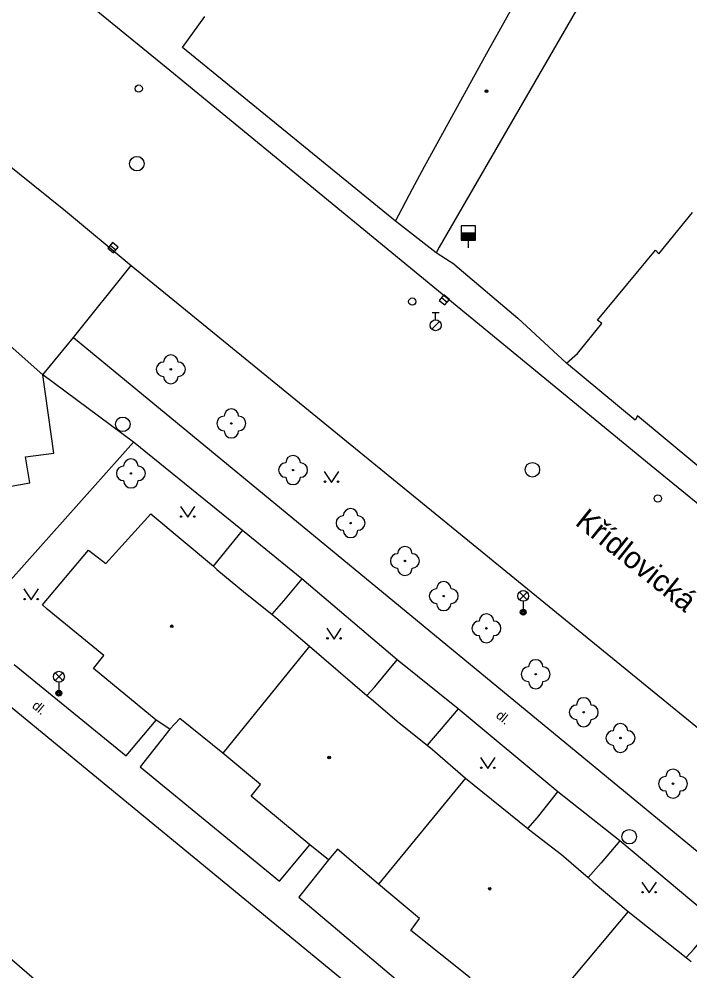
# Model space of a CAD drawing. Extents: x -598932 to -598196, y -1162207 to -1161504.
# Drawn here: x -598487.7 to -598441.5, y -1161944.1 to -1161878.5 of the extents above; entities that cross this region are included whole.
import ezdxf

# ---------------------------------------------------------------- set-up
doc = ezdxf.new("R2010")
doc.units = 0
for name, color, linetype in [('Level 22', 7, 'Continuous'), ('Level 27', 7, 'Continuous'), ('Level 28', 7, 'Continuous'), ('Level 33', 7, 'Continuous'), ('Level 36', 7, 'Continuous'), ('Level 39', 7, 'Continuous'), ('specificka linie pasportu komunikaci', 7, 'Continuous'), ('TM - budovy zdene_ betonove - VP', 7, 'Continuous'), ('TM - chodniky - VP', 7, 'Continuous'), ('TM - komunikace - VP', 7, 'Continuous'), ('TM - plot dreveny_ kovovy - VP', 7, 'Continuous'), ('TM - plot zdeny_ ohradni zed - VP', 7, 'Continuous'), ('TM - popis povrchu', 7, 'Continuous'), ('TM - rozhrani ploch obecne - VP', 7, 'Continuous'), ('TM - vjezd na pozemek', 7, 'Continuous'), ('ulice', 7, 'Continuous')]:
    doc.layers.add(name, color=color, linetype=linetype)

msp = doc.modelspace()

# ---------------------------------------------------------------- linework, layer by layer
at = {"layer": 'Level 22'}
for centre in [(-598477.28, -1161902.63), (-598473.11, -1161906.36), (-598480.03, -1161909.8), (-598468.86, -1161909.57), (-598464.9, -1161913.22), (-598461.16, -1161915.83), (-598458.48, -1161918.25), (-598455.54, -1161920.47), (-598452.15, -1161923.63), (-598448.84, -1161926.25), (-598446.31, -1161928.02), (-598442.69, -1161931.17)]:
    msp.add_circle(centre, 0.05, dxfattribs=at)
for centre, start, end in [((-598477.28, -1161902.13), 0, 180), ((-598477.78, -1161902.63), 90, 270), ((-598476.78, -1161902.63), 270, 90), ((-598477.28, -1161903.13), 180, 0), ((-598473.61, -1161906.36), 90, 270), ((-598473.11, -1161905.86), 0, 180), ((-598472.61, -1161906.36), 270, 90), ((-598473.11, -1161906.86), 180, 0), ((-598468.86, -1161909.07), 0, 180), ((-598480.03, -1161909.3), 0, 180), ((-598469.36, -1161909.57), 90, 270), ((-598468.36, -1161909.57), 270, 90), ((-598480.53, -1161909.8), 90, 270), ((-598479.53, -1161909.8), 270, 90), ((-598480.03, -1161910.3), 180, 0), ((-598468.86, -1161910.07), 180, 0), ((-598464.9, -1161912.72), 0, 180), ((-598465.4, -1161913.22), 90, 270), ((-598464.4, -1161913.22), 270, 90), ((-598464.9, -1161913.72), 180, 0), ((-598461.16, -1161915.33), 0, 180), ((-598461.66, -1161915.83), 90, 270), ((-598460.66, -1161915.83), 270, 90), ((-598461.16, -1161916.33), 180, 0), ((-598458.98, -1161918.25), 90, 270), ((-598458.48, -1161917.75), 0, 180), ((-598457.98, -1161918.25), 270, 90), ((-598458.48, -1161918.75), 180, 0), ((-598455.54, -1161919.97), 0, 180), ((-598456.04, -1161920.47), 90, 270), ((-598455.04, -1161920.47), 270, 90), ((-598455.54, -1161920.97), 180, 0), ((-598452.15, -1161923.13), 0, 180), ((-598452.65, -1161923.63), 90, 270), ((-598451.65, -1161923.63), 270, 90), ((-598452.15, -1161924.13), 180, 0), ((-598448.84, -1161925.75), 0, 180), ((-598449.34, -1161926.25), 90, 270), ((-598448.34, -1161926.25), 270, 90), ((-598448.84, -1161926.75), 180, 0), ((-598446.81, -1161928.02), 90, 270), ((-598446.31, -1161927.52), 0, 180), ((-598445.81, -1161928.02), 270, 90), ((-598446.31, -1161928.52), 180, 0), ((-598442.69, -1161930.67), 0, 180), ((-598443.19, -1161931.17), 90, 270), ((-598442.19, -1161931.17), 270, 90), ((-598442.69, -1161931.67), 180, 0)]:
    msp.add_arc(centre, 0.5, start, end, dxfattribs=at)
at = {"layer": 'Level 27'}
for p, q in [((-598481.463, -1161894.091), (-598481.077, -1161894.409)), ((-598458.643, -1161897.691), (-598458.257, -1161898.009))]:
    msp.add_line(p, q, dxfattribs=at)
for points in [[(-598481.622, -1161894.283), (-598481.237, -1161894.602), (-598480.918, -1161894.217), (-598481.303, -1161893.898)], [(-598458.802, -1161897.883), (-598458.417, -1161898.202), (-598458.098, -1161897.817), (-598458.483, -1161897.498)]]:
    msp.add_lwpolyline(points, close=True, dxfattribs=at)
for centre in [(-598479.62, -1161888.47), (-598480.59, -1161906.42), (-598452.38, -1161909.55), (-598445.71, -1161934.82)]:
    msp.add_circle(centre, 0.5, dxfattribs=at)
at = {"layer": 'Level 28'}
for p, q in [((-598457.29, -1161893.24), (-598456.29, -1161893.24)), ((-598457.29, -1161893.29), (-598456.29, -1161893.29)), ((-598457.29, -1161893.34), (-598456.29, -1161893.34)), ((-598457.29, -1161893.39), (-598456.29, -1161893.39)), ((-598457.29, -1161893.44), (-598456.29, -1161893.44)), ((-598457.29, -1161893.49), (-598456.29, -1161893.49)), ((-598457.29, -1161893.54), (-598456.29, -1161893.54)), ((-598457.29, -1161893.59), (-598456.29, -1161893.59)), ((-598457.29, -1161893.64), (-598456.29, -1161893.64)), ((-598457.29, -1161893.69), (-598456.29, -1161893.69)), ((-598456.79, -1161893.74), (-598456.79, -1161894.27)), ((-598459.29, -1161898.725), (-598458.79, -1161898.725)), ((-598459.04, -1161899.225), (-598459.04, -1161898.725)), ((-598459.298, -1161899.872), (-598458.768, -1161899.342))]:
    msp.add_line(p, q, dxfattribs=at)
msp.add_lwpolyline([(-598457.29, -1161893.74), (-598456.29, -1161893.74), (-598456.29, -1161892.74), (-598457.29, -1161892.74)], close=True, dxfattribs=at)
for centre, radius in [((-598479.49, -1161883.3), 0.25), ((-598460.65, -1161897.97), 0.25), ((-598459.04, -1161899.6), 0.375), ((-598443.74, -1161911.53), 0.25)]:
    msp.add_circle(centre, radius, dxfattribs=at)
at = {"layer": 'Level 33'}
for p, q in [((-598453.275, -1161918.5), (-598452.745, -1161917.97)), ((-598453.275, -1161917.97), (-598452.745, -1161918.5)), ((-598453.01, -1161918.61), (-598453.01, -1161919.36)), ((-598485.255, -1161924.07), (-598484.725, -1161923.54)), ((-598485.255, -1161923.54), (-598484.725, -1161924.07)), ((-598484.99, -1161924.18), (-598484.99, -1161924.93))]:
    msp.add_line(p, q, dxfattribs=at)
for centre, radius in [((-598453.01, -1161918.235), 0.375), ((-598453.01, -1161919.36), 0.2), ((-598453.01, -1161919.36), 0.145), ((-598453.01, -1161919.36), 0.0876), ((-598484.99, -1161923.805), 0.375), ((-598484.99, -1161924.93), 0.2), ((-598484.99, -1161924.93), 0.145), ((-598484.99, -1161924.93), 0.0876)]:
    msp.add_circle(centre, radius, dxfattribs=at)
at = {"layer": 'Level 36'}
for points in [[(-598466.71, -1161909.67), (-598466.21, -1161910.42), (-598465.71, -1161909.67)], [(-598476.62, -1161912.07), (-598476.12, -1161912.82), (-598475.62, -1161912.07)], [(-598487.4, -1161917.76), (-598486.9, -1161918.51), (-598486.4, -1161917.76)], [(-598466.54, -1161920.46), (-598466.04, -1161921.21), (-598465.54, -1161920.46)], [(-598455.95, -1161929.37), (-598455.45, -1161930.12), (-598454.95, -1161929.37)], [(-598444.84, -1161937.94), (-598444.34, -1161938.69), (-598443.84, -1161937.94)]]:
    msp.add_lwpolyline(points, dxfattribs=at)
for centre in [(-598466.66, -1161910.37), (-598465.761, -1161910.37), (-598476.57, -1161912.77), (-598475.671, -1161912.77), (-598487.35, -1161918.46), (-598486.451, -1161918.46), (-598466.49, -1161921.16), (-598465.591, -1161921.16), (-598455.9, -1161930.07), (-598455.001, -1161930.07), (-598444.79, -1161938.64), (-598443.891, -1161938.64)]:
    msp.add_circle(centre, 0.05, dxfattribs=at)
at = {"layer": 'Level 39'}
for centre, radius in [((-598455.54, -1161883.48), 0.09), ((-598455.54, -1161883.48), 0.0398), ((-598477.22, -1161920.33), 0.09), ((-598477.22, -1161920.33), 0.0398), ((-598466.37, -1161929.37), 0.09), ((-598466.37, -1161929.37), 0.0398), ((-598455.32, -1161938.4), 0.09), ((-598455.32, -1161938.4), 0.0398)]:
    msp.add_circle(centre, radius, dxfattribs=at)
at = {"layer": 'specificka linie pasportu komunikaci'}
for points in [[(-598481.55, -1161894.196), (-598481.622, -1161894.283), (-598481.237, -1161894.602), (-598481.166, -1161894.516)], [(-598486.09, -1161903.02), (-598494.7, -1161895.38)], [(-598468.25, -1161917.06), (-598472.34, -1161913.74)], [(-598457.49, -1161926.01), (-598461.68, -1161922.63)], [(-598446.36, -1161935.11), (-598450.63, -1161931.72)]]:
    msp.add_lwpolyline(points, dxfattribs=at)
at = {"layer": 'TM - budovy zdene_ betonove - VP'}
for points in [[(-598455.55, -1161880.91), (-598449.31, -1161869.76)], [(-598445.71, -1161871.58), (-598458.8, -1161894.23)], [(-598459.81, -1161888.67), (-598455.55, -1161880.91)], [(-598460.63, -1161890.21), (-598459.81, -1161888.67)], [(-598461.81, -1161892.42), (-598460.63, -1161890.21)], [(-598443.66, -1161894.68), (-598441.34, -1161891.84)], [(-598459.01, -1161894.6), (-598461.81, -1161892.42)], [(-598458.8, -1161894.23), (-598459.01, -1161894.6)], [(-598447.89, -1161899.25), (-598443.9, -1161894.43)], [(-598443.9, -1161894.43), (-598443.66, -1161894.68)], [(-598447.59, -1161899.48), (-598447.89, -1161899.25)], [(-598449.27, -1161901.55), (-598447.59, -1161899.48)], [(-598450.04, -1161902.22), (-598449.27, -1161901.55)], [(-598445.31, -1161906.14), (-598450.04, -1161902.22)], [(-598445.14, -1161905.83), (-598445.31, -1161906.14)], [(-598437.1, -1161912.52), (-598445.14, -1161905.83)], [(-598481.76, -1161916.01), (-598478.66, -1161912.59)], [(-598478.66, -1161912.59), (-598474.34, -1161916.19)], [(-598486.12, -1161918.85), (-598482.95, -1161915.09)], [(-598482.95, -1161915.09), (-598481.76, -1161916.01)], [(-598474.34, -1161916.19), (-598474.12, -1161916.41)], [(-598474.12, -1161916.41), (-598472.13, -1161918.05)], [(-598472.13, -1161918.05), (-598470.33, -1161919.49)], [(-598485.8, -1161919.16), (-598486.12, -1161918.85)], [(-598481.9, -1161922.34), (-598485.8, -1161919.16)], [(-598470.33, -1161919.49), (-598470.04, -1161919.72)], [(-598470.04, -1161919.72), (-598467.74, -1161921.69)], [(-598467.74, -1161921.69), (-598473.7, -1161929.07)], [(-598467.74, -1161921.69), (-598463.78, -1161925.1)], [(-598482.61, -1161923.23), (-598481.9, -1161922.34)], [(-598478.28, -1161926.8), (-598482.61, -1161923.23)], [(-598463.78, -1161925.1), (-598463.47, -1161925.35)], [(-598463.47, -1161925.35), (-598461.55, -1161926.97)], [(-598477.35, -1161927.42), (-598478.28, -1161926.8)], [(-598476.65, -1161926.67), (-598477.35, -1161927.42)], [(-598473.7, -1161929.07), (-598476.65, -1161926.67)], [(-598461.55, -1161926.97), (-598459.62, -1161928.51)], [(-598459.62, -1161928.51), (-598459.26, -1161928.81)], [(-598459.26, -1161928.81), (-598456.99, -1161930.79)], [(-598471.11, -1161931.23), (-598473.7, -1161929.07)], [(-598456.99, -1161930.79), (-598462.98, -1161938.09)], [(-598456.99, -1161930.79), (-598452.69, -1161934.26)], [(-598471.75, -1161932.03), (-598471.11, -1161931.23)], [(-598467.7, -1161935.39), (-598471.75, -1161932.03)], [(-598452.69, -1161934.26), (-598452.34, -1161934.52)], [(-598452.34, -1161934.52), (-598450.37, -1161936.04)], [(-598466.41, -1161936.41), (-598467.7, -1161935.39)], [(-598465.79, -1161935.67), (-598466.41, -1161936.41)], [(-598462.98, -1161938.09), (-598465.79, -1161935.67)], [(-598450.37, -1161936.04), (-598448.54, -1161937.62)], [(-598460.15, -1161940.46), (-598462.98, -1161938.09)], [(-598448.54, -1161937.62), (-598448.2, -1161937.94)], [(-598448.2, -1161937.94), (-598445.78, -1161939.96)], [(-598445.78, -1161939.96), (-598451.87, -1161947.22)], [(-598445.78, -1161939.96), (-598441.79, -1161943.14)], [(-598460.76, -1161941.27), (-598460.15, -1161940.46)], [(-598456.67, -1161944.53), (-598460.76, -1161941.27)], [(-598441.79, -1161943.14), (-598441.45, -1161943.41)]]:
    msp.add_lwpolyline(points, dxfattribs=at)
at = {"layer": 'TM - chodniky - VP'}
for points in [[(-598461.81, -1161892.42), (-598476.48, -1161880.46), (-598474.94, -1161878.34)], [(-598483.98, -1161900.43), (-598423.59, -1161950.19)], [(-598479.84, -1161907.65), (-598491.16, -1161920.33)], [(-598474.34, -1161916.19), (-598472.34, -1161913.74), (-598479.84, -1161907.65)], [(-598463.78, -1161925.1), (-598463.23, -1161924.49), (-598461.68, -1161922.63), (-598468.25, -1161917.06), (-598469.51, -1161918.57), (-598470.33, -1161919.49)], [(-598488.07, -1161922.95), (-598480.35, -1161929.24), (-598478.28, -1161926.8)], [(-598452.69, -1161934.26), (-598452.02, -1161933.49), (-598450.63, -1161931.72), (-598457.49, -1161926.01), (-598458.8, -1161927.55), (-598459.62, -1161928.51)], [(-598477.35, -1161927.42), (-598479.4, -1161930.01), (-598469.79, -1161937.89), (-598467.7, -1161935.39)], [(-598499.07, -1161933.94), (-598486.35, -1161944.91)], [(-598441.79, -1161943.14), (-598441.23, -1161942.53), (-598439.69, -1161940.68), (-598446.36, -1161935.11), (-598447.63, -1161936.62), (-598448.54, -1161937.62)], [(-598466.41, -1161936.41), (-598468.46, -1161938.98), (-598458.84, -1161947.1), (-598456.67, -1161944.53)]]:
    msp.add_lwpolyline(points, dxfattribs=at)
at = {"layer": 'TM - komunikace - VP'}
for points in [[(-598511.45, -1161854.21), (-598508.79, -1161856.41), (-598477.35, -1161882.04), (-598444.2, -1161909.25), (-598424.09, -1161925.65), (-598407.41, -1161939.34), (-598401.94, -1161943.6)], [(-598483.98, -1161900.43), (-598480.01, -1161895.48)], [(-598480.01, -1161895.48), (-598430.9, -1161935.53), (-598419.47, -1161944.82)], [(-598486.09, -1161903.02), (-598483.98, -1161900.43)], [(-598490.63, -1161914.83), (-598490.94, -1161913.06), (-598488.81, -1161912.71), (-598489.2, -1161910.83), (-598486.99, -1161910.45), (-598487.29, -1161908.67), (-598485.34, -1161908.4), (-598486.09, -1161903.02)]]:
    msp.add_lwpolyline(points, dxfattribs=at)
at = {"layer": 'TM - plot dreveny_ kovovy - VP'}
msp.add_lwpolyline([(-598489.65, -1161924.78), (-598452.66, -1161955.16)], dxfattribs=at)
at = {"layer": 'TM - plot zdeny_ ohradni zed - VP'}
for points in [[(-598457.72, -1161895.44), (-598459.01, -1161894.6)], [(-598450.04, -1161902.22), (-598453.39, -1161899.11)]]:
    msp.add_lwpolyline(points, dxfattribs=at)
at = {"layer": 'TM - rozhrani ploch obecne - VP'}
for points in [[(-598488.77, -1161888.33), (-598484.53, -1161891.71), (-598480.01, -1161895.48)], [(-598479.84, -1161907.65), (-598486.09, -1161903.02)]]:
    msp.add_lwpolyline(points, dxfattribs=at)
at = {"layer": 'TM - vjezd na pozemek'}
msp.add_lwpolyline([(-598457.72, -1161895.44), (-598453.39, -1161899.11)], dxfattribs=at)

# ---------------------------------------------------------------- texts
at = {"layer": 'TM - popis povrchu'}
for p in [(-598486.89, -1161925.89), (-598454.94, -1161926.56)]:
    msp.add_text('dl.', height=0.65, rotation=319.99, dxfattribs=at).set_placement(p)
at = {"layer": 'ulice'}
msp.add_text('Křídlovická', height=1.5, rotation=321.29046, dxfattribs=at).set_placement((-598449.507, -1161913.286))

doc.saveas('drawing.dxf')
